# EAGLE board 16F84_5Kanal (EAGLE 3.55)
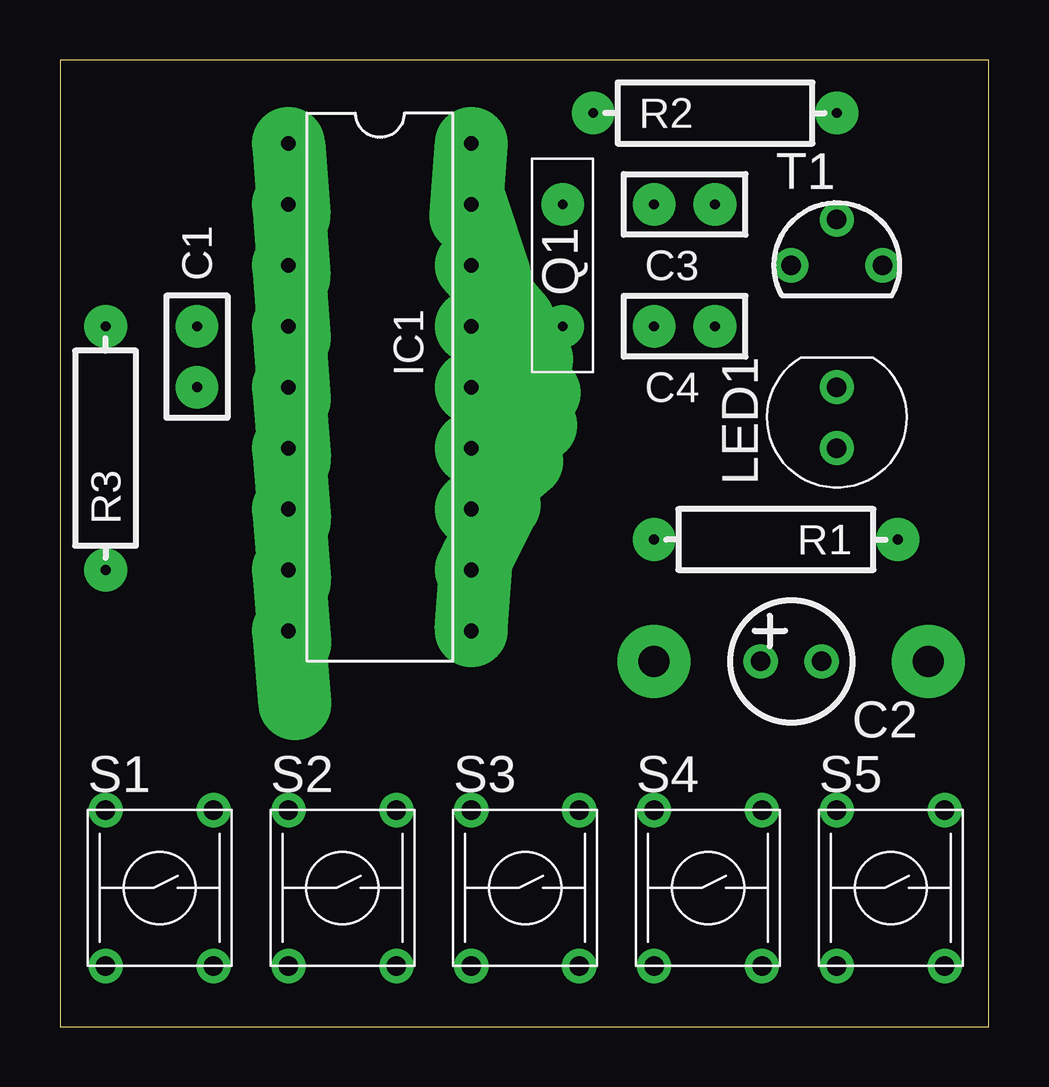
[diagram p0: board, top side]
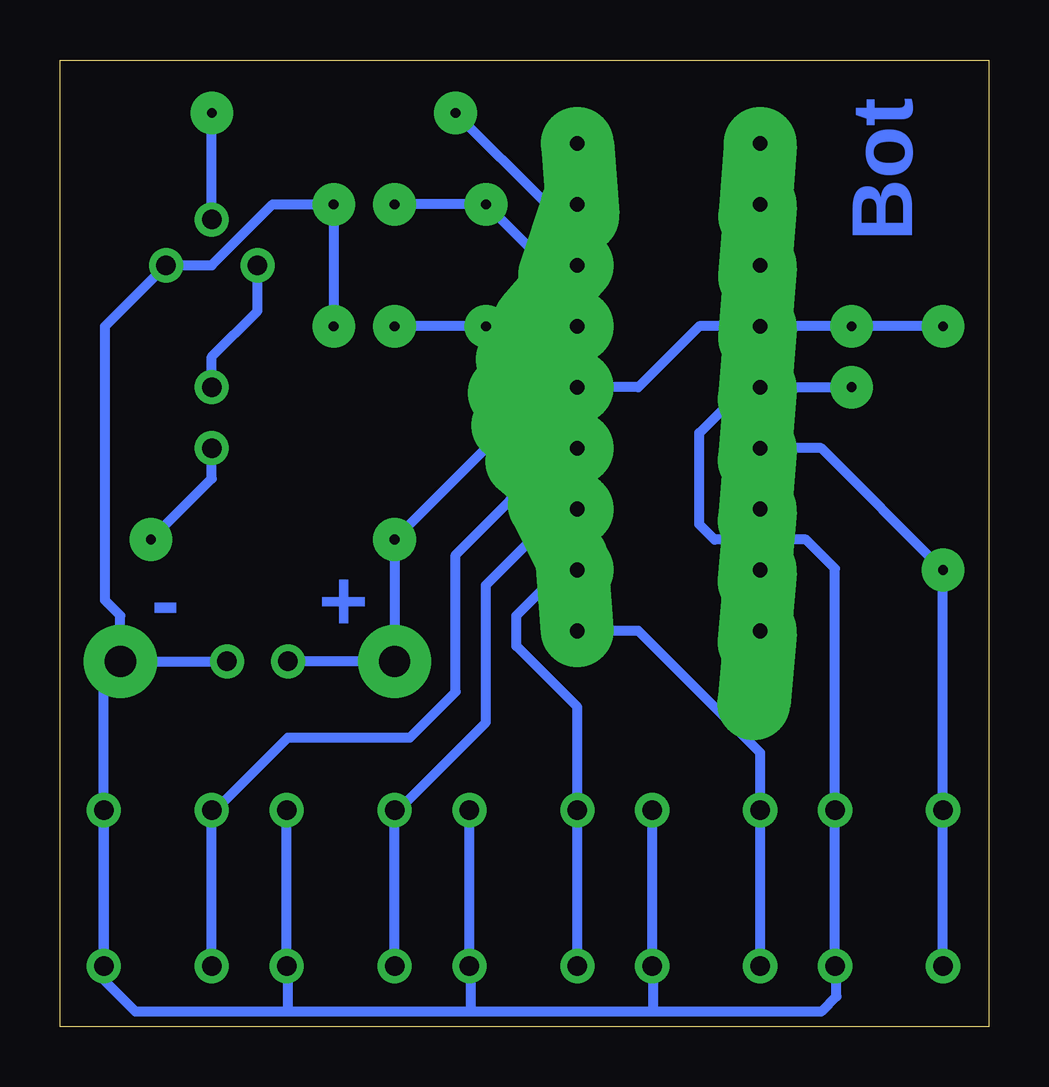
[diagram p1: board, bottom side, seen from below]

Size 38.72 x 40.31 mm. Coordinates in mm from the lower left corner, seen from the top.
Outline: 0,0 38.72,0 38.72,40.31 0,40.31 0,0
Copper layers used: Bottom

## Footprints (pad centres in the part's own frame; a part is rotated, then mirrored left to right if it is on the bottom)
RM2,5 = drill 0.406 pad 1.778 round:  0,0;  2.54,0
KO01 = drill 0.813 pad 1.422 round:  0,0;  2.54,0
L-18B = drill 0.61 pad 3.048 offset:  0,0;  2.54,0;  15.24,0;  17.78,0;  5.08,0;  7.62,0;  12.7,0;  10.16,0;  20.32,0;  20.32,7.62;  17.78,7.62;  15.24,7.62;  12.7,7.62;  10.16,7.62;  7.62,7.62;  5.08,7.62;  2.54,7.62;  0,7.62
D_5MM = drill 0.813 pad 1.422 round:  -1.27,0;  1.27,0
GEL = drill 1.295 pad 3.048 round:  0,0
ARZ_ST = drill 0.406 pad 1.778 round:  0,0;  5.08,0
S04 = drill 0.406 pad 1.778 round:  0,0;  10.16,0
US = drill 0.813 pad 1.422 round:  0,0;  4.5,0;  4.5,6.5;  0,6.5
92 = drill 0.813 pad 1.422 round:  -0.635,0;  1.27,1.905;  3.175,0

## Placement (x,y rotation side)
C1  C100NK  [RM2,5]  5.71,26.67 90 top
C2  100u  [KO01]  29.21,15.24 0 top
C3  27p  [RM2,5]  27.3,34.29 180 top
C4  27p  [RM2,5]  27.3,29.21 180 top
IC1  16F84P  [L-18B]  9.53,36.83 270 top
LED1  LD274  [D_5MM]  32.38,25.4 90 top
N1  +  [GEL]  24.77,15.24 0 top
N2  -  [GEL]  36.2,15.24 0 top
Q1  4MHz  [ARZ_ST]  20.95,29.21 90 top
R1  ???  [S04]  34.92,20.32 180 top
R2  1k  [S04]  22.23,38.1 0 top
R3  100k  [S04]  1.91,19.05 90 top
S1  Code3  [US]  1.91,2.54 0 top
S2  Code4  [US]  9.53,2.54 0 top
S3  Code5  [US]  17.14,2.54 0 top
S4  Code6  [US]  24.77,2.54 0 top
S5  Code7  [US]  32.38,2.54 0 top
T1  BC337  [92]  31.11,31.75 0 top

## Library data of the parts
C1 C2 LED1 N1 N2 R1 R2 T1 = holgnorm
C3 C4 IC1 Q1 R3 = holg_plt
S1-S5 = taster1

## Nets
+UB: C1. C2. IC1. N1. R1. R3.
GND: C1. C2. C3. C4. IC1. N2. S1. S2. S3. S4. S5. T1.
N$2: R2. T1.
N$4: LED1. T1.
N$5: LED1. R1.
N$6: IC1. R2.
N$7: C3. IC1. Q1.
N$8: C4. IC1. Q1.
N$10: IC1. R3. S1.
N$11: IC1. S2.
N$12: IC1. S3.
N$13: IC1. S4.
N$14: IC1. S5.

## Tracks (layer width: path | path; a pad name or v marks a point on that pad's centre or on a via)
+UB
  Bottom 0.406: 29.21,15.24 N1. R1. 18.41,26.67 17.14,26.67 14.61,26.67 12.06,29.21 9.53,29.21 C1. R3.
GND
  Bottom 0.406: 5.71,26.67 9.53,26.67 10.16,26.67 12.06,24.77 12.06,20.95 11.43,20.32 7.62,20.32 6.41,19.11 6.41,9.04 6.41,8.95 6.35,8.89 6.41,8.84 6.41,2.54 6.35,2.54 6.35,1.27 6.99,0.64 13.97,0.64 | 14.03,9.04 14.03,8.95 13.97,8.89 14.03,8.84 14.03,2.54 13.97,2.54 13.97,0.64 | 21.64,9.04 21.64,8.95 21.59,8.89 21.64,8.84 21.64,2.54 21.59,2.54 21.59,0.64 | 29.27,9.04 29.27,8.95 29.21,8.89 29.27,8.84 29.27,2.54 29.21,2.54 29.21,0.64 | 36.88,9.04 36.88,8.95 36.83,8.89 36.88,8.84 36.88,2.54 | 27.3,29.21 27.3,34.29 29.84,34.29 32.38,31.75 T1. 36.83,29.21 36.83,17.78 36.2,17.14 N2. | 36.88,9.04 36.88,2.6 36.83,2.54 36.83,1.91 35.56,0.64 29.21,0.64 | 21.59,0.64 29.21,0.64 | 13.97,0.64 21.59,0.64 | N2. C2. | 36.88,9.04 36.88,14.55 N2.
N$2
  Bottom 0.406: 32.38,33.66 R2.
N$4
  Bottom 0.406: LED1. 32.38,27.94 30.48,29.84 30.48,31.75
N$5
  Bottom 0.406: 34.92,20.32 32.38,22.86 32.38,24.13
N$6
  Bottom 0.406: 17.14,34.29 18.41,34.29 22.23,38.1
N$7
  Bottom 0.406: 17.14,31.75 18.41,31.75 Q1. C3.
N$8
  Bottom 0.406: 17.14,29.21 20.95,29.21 C4.
N$10
  Bottom 0.406: 1.91,2.54 1.91,8.89 | 1.91,8.89 S1. | 1.91,8.89 1.91,19.05 6.99,24.13 9.53,24.13
N$11
  Bottom 0.406: 9.53,2.54 9.53,8.89 | 17.14,16.51 14.61,16.51 9.53,11.43 9.53,8.89 | 9.53,8.89 S2.
N$12
  Bottom 0.406: 17.14,2.54 17.14,8.89 | 17.14,19.05 17.78,19.05 19.68,17.14 19.68,15.88 17.14,13.34 17.14,8.89 | 17.14,8.89 S3.
N$13
  Bottom 0.406: 24.77,2.54 24.77,8.89 | 17.14,21.59 17.78,21.59 20.95,18.41 20.95,12.7 24.77,8.89 | 24.77,8.89 S4.
N$14
  Bottom 0.406: 32.38,2.54 32.38,8.89 | 17.14,24.13 17.78,24.13 22.23,19.68 22.23,13.97 24.13,12.06 29.21,12.06 32.38,8.89 | 32.38,8.89 S5.

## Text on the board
Bottom: Bot | + | -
